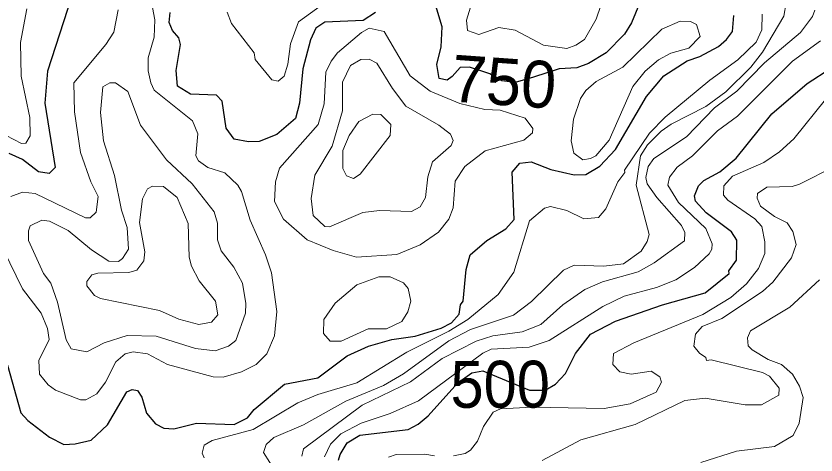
# Model space of a CAD drawing. Extents: x 763.2 to 816.8, y 7896.5 to 7952.7.
# Drawn here: x 788.764 to 791.494, y 7916.414 to 7917.911 of the extents above; entities that cross this region are included whole.
import ezdxf
from ezdxf.enums import TextEntityAlignment as Align

# ---------------------------------------------------------------- set-up
doc = ezdxf.new("R2010")
doc.units = 0
doc.header["$LTSCALE"] = 0.064
doc.layers.add('1', color=7, linetype='Continuous', lineweight=25)
doc.layers.add('2', color=7, linetype='Continuous', lineweight=13)
doc.layers.add('61', color=7, linetype='Continuous')

msp = doc.modelspace()

# ---------------------------------------------------------------- linework, layer by layer
at = {"layer": '1'}
for points in [[(788.9532, 7917.9764), (788.8718, 7917.7233), (788.862, 7917.6141), (788.8983, 7917.3951), (788.8775, 7917.3735), (788.8407, 7917.3792), (788.7863, 7917.4224), (788.7412, 7917.4422)], [(790.8995, 7917.9748), (790.8639, 7917.8884), (790.8401, 7917.8489), (790.7781, 7917.7858), (790.7169, 7917.7496), (790.6779, 7917.735), (790.6177, 7917.7315), (790.5297, 7917.7032), (790.4675, 7917.6845), (790.4219, 7917.6907), (790.3804, 7917.7136), (790.3119, 7917.7364), (790.2798, 7917.7354), (790.2521, 7917.7053), (790.2347, 7917.6927), (790.2079, 7917.6978), (790.1997, 7917.7465), (790.2143, 7917.8068), (790.2176, 7917.8744), (790.1967, 7917.9459)], [(788.7355, 7916.7201), (788.7801, 7916.558), (788.804, 7916.5314), (788.8784, 7916.4743), (788.9268, 7916.4498), (788.9662, 7916.4515), (789.0207, 7916.4639), (789.0758, 7916.5165), (789.1419, 7916.6289), (789.16, 7916.6367), (789.1789, 7916.6332), (789.194, 7916.6114), (789.2092, 7916.5563), (789.2405, 7916.5199), (789.2689, 7916.5047), (789.3025, 7916.5026), (789.3797, 7916.5217), (789.5084, 7916.5173), (789.5537, 7916.5401), (789.5769, 7916.5693), (789.6804, 7916.6548), (789.7937, 7916.6767), (789.894, 7916.7519), (789.9672, 7916.7846), (790.0468, 7916.8079), (790.1266, 7916.8196), (790.2143, 7916.8469), (790.2502, 7916.8647), (790.2761, 7916.8942), (790.2802, 7916.9254), (790.29, 7916.9386), (790.3001, 7917.047), (790.3132, 7917.0971), (790.3707, 7917.1453), (790.4355, 7917.1855), (790.464, 7917.2174), (790.4566, 7917.3787), (790.4832, 7917.4093), (790.5223, 7917.4142), (790.5884, 7917.3882), (790.6688, 7917.37), (790.7081, 7917.3705), (790.7563, 7917.3988), (790.809, 7917.4564), (790.9158, 7917.6372), (790.9741, 7917.707), (791.0544, 7917.7586), (791.0969, 7917.7733), (791.1615, 7917.8075), (791.1885, 7917.8313), (791.2082, 7917.8591), (791.2135, 7917.9131)], [(789.9909, 7917.9238), (789.9486, 7917.8963), (789.8175, 7917.8909), (789.7875, 7917.8696), (789.7687, 7917.8304), (789.7428, 7917.7311), (789.7311, 7917.6141), (789.7183, 7917.5613), (789.6535, 7917.507), (789.5939, 7917.4837), (789.5579, 7917.4818), (789.5085, 7917.4915), (789.4813, 7917.5291), (789.468, 7917.6209), (789.4481, 7917.6416), (789.3599, 7917.6446), (789.3154, 7917.6724), (789.3106, 7917.7251), (789.3251, 7917.8146), (789.3193, 7917.8372), (789.2977, 7917.8624), (789.2864, 7917.8893), (789.2905, 7917.9236)], [(789.8647, 7916.396), (789.8698, 7916.4158), (789.8937, 7916.4547), (789.9369, 7916.4811), (790.1027, 7916.5007), (790.1365, 7916.5183), (790.1704, 7916.5471), (790.2719, 7916.6599), (790.3198, 7916.6936), (790.3574, 7916.7011), (790.516, 7916.6347), (790.5699, 7916.6346), (790.6044, 7916.6555), (790.6387, 7916.6916), (790.6728, 7916.76), (790.7247, 7916.8262), (790.8101, 7916.8705), (790.9704, 7916.9262), (791.1155, 7916.9673), (791.1978, 7917.0325), (791.1962, 7917.0418), (791.2219, 7917.078), (791.2233, 7917.1461), (791.2048, 7917.1748), (791.1189, 7917.2394), (791.0827, 7917.2792), (791.0792, 7917.2974), (791.0922, 7917.3321), (791.1113, 7917.3498), (791.1655, 7917.3794), (791.2207, 7917.4263), (791.3431, 7917.5781), (791.464, 7917.6809), (791.5445, 7917.7334)]]:
    msp.add_lwpolyline(points, dxfattribs=at)
at = {"layer": '2'}
for points in [[(789.2187, 7918.0024), (789.2382, 7917.8982), (789.2352, 7917.8397), (789.2153, 7917.7686), (789.2153, 7917.7241), (789.2237, 7917.6832), (789.236, 7917.6583), (789.3661, 7917.5538), (789.3844, 7917.5096), (789.3782, 7917.4348), (789.3871, 7917.4168), (789.4183, 7917.3947), (789.4771, 7917.3765), (789.5207, 7917.3341), (789.5339, 7917.3124), (789.5635, 7917.2145), (789.6157, 7917.0969), (789.636, 7917.0357), (789.6539, 7916.903), (789.646, 7916.8201), (789.6204, 7916.759), (789.5839, 7916.7229), (789.5331, 7916.697), (789.4709, 7916.6797), (789.4373, 7916.6799), (789.2805, 7916.7228), (789.2129, 7916.7586), (789.1637, 7916.7652), (789.1364, 7916.7584), (789.1051, 7916.732), (789.0689, 7916.6617), (789.0399, 7916.6227), (789.0029, 7916.6015), (788.9843, 7916.6022), (788.8986, 7916.6348), (788.874, 7916.6531), (788.844, 7916.6897), (788.8423, 7916.7355), (788.8767, 7916.8078), (788.8719, 7916.8451), (788.8501, 7916.8977), (788.7864, 7916.9805), (788.7211, 7917.1138)], [(789.4848, 7917.9246), (789.4989, 7917.8864), (789.5766, 7917.7854), (789.5801, 7917.7634), (789.6368, 7917.6937), (789.6584, 7917.689), (789.6795, 7917.7058), (789.6919, 7917.747), (789.7003, 7917.816), (789.7283, 7917.8918), (789.8589, 7917.9875)], [(788.8108, 7917.5648), (788.7816, 7917.7062), (788.7797, 7917.8212), (788.8011, 7917.9362)], [(790.3195, 7917.956), (790.3017, 7917.8975), (790.3051, 7917.8621), (790.3437, 7917.8482)], [(790.6745, 7917.8123), (790.7033, 7917.8315), (790.7432, 7917.9001), (790.7598, 7917.9469)], [(791.3924, 7917.9568), (791.3844, 7917.9108), (791.3111, 7917.7877), (791.2712, 7917.7365), (791.186, 7917.6528), (791.1177, 7917.6029), (790.9994, 7917.542), (790.9652, 7917.5181), (790.9182, 7917.4716), (790.8948, 7917.4349), (790.88, 7917.3337), (790.9242, 7917.166)], [(788.7462, 7917.2953), (788.7867, 7917.3105), (788.8297, 7917.306), (789.001, 7917.2223), (789.0166, 7917.2225), (789.0378, 7917.2426), (789.0442, 7917.2952), (789.0198, 7917.3454), (788.9847, 7917.4462), (788.9636, 7917.5843), (788.961, 7917.6832), (789.0711, 7917.8145), (789.0974, 7917.8561), (789.1132, 7917.9322)], [(791.3105, 7917.9172), (791.3088, 7917.8647), (791.2891, 7917.8218), (791.2272, 7917.7618), (791.1315, 7917.692), (790.9792, 7917.5661), (790.925, 7917.5117), (790.8402, 7917.3859), (790.8417, 7917.3776), (790.818, 7917.3459), (790.7767, 7917.2539), (790.7517, 7917.224), (790.7012, 7917.219), (790.6433, 7917.2482), (790.5873, 7917.2611), (790.5671, 7917.2553), (790.5166, 7917.2126), (790.4628, 7917.037), (790.4097, 7916.9607), (790.3059, 7916.8762), (790.2406, 7916.8358), (790.0973, 7916.7649), (789.9273, 7916.6593), (789.7938, 7916.6205), (789.726, 7916.5914), (789.5729, 7916.5003), (789.433, 7916.4635), (789.406, 7916.4476), (789.3995, 7916.4198), (789.4063, 7916.4042)], [(789.7397, 7916.4092), (789.7447, 7916.4347), (789.9455, 7916.5831), (790.1099, 7916.6637), (790.2181, 7916.7434), (790.3342, 7916.8018), (790.3906, 7916.8206), (790.4912, 7916.8343), (790.5552, 7916.8586), (790.6303, 7916.9261), (790.7046, 7916.9779), (790.7647, 7917.0039), (790.8872, 7917.039), (790.9414, 7917.0695), (791.0455, 7917.1447), (791.046, 7917.1733), (791.0348, 7917.1968), (790.9503, 7917.2917), (790.918, 7917.3388), (790.9131, 7917.3608), (790.9214, 7917.3981), (790.94, 7917.4255), (791.0521, 7917.4992), (791.1475, 7917.5978), (791.223, 7917.6554), (791.3178, 7917.7516), (791.4404, 7917.8548), (791.4822, 7917.9094), (791.4897, 7917.9311)], [(790.3437, 7917.8482), (790.411, 7917.8725), (790.4668, 7917.8629), (790.5635, 7917.8119), (790.6431, 7917.8009), (790.6745, 7917.8123)], [(791.0199, 7917.3961), (791.0728, 7917.4345), (791.1577, 7917.5192), (791.226, 7917.57), (791.413, 7917.7577), (791.5089, 7917.8264)], [(791.5266, 7917.6268), (791.4184, 7917.4927), (791.3686, 7917.4476), (791.3155, 7917.4111), (791.2091, 7917.3644), (791.1793, 7917.3324), (791.1777, 7917.3), (791.1929, 7917.2826), (791.2854, 7917.2191), (791.309, 7917.1928), (791.3188, 7917.1408), (791.3186, 7917.1015), (791.2973, 7917.0495), (791.2569, 7916.9975), (791.203, 7916.9512), (791.1073, 7916.8927), (790.8725, 7916.7966), (790.803, 7916.7601), (790.8002, 7916.7228), (790.8243, 7916.6976), (790.8627, 7916.6897), (790.9314, 7916.6994), (790.9611, 7916.6804), (790.9666, 7916.6626), (790.9488, 7916.6275), (790.8594, 7916.5879), (790.7704, 7916.5717), (790.5257, 7916.5768), (790.4173, 7916.5707), (790.3923, 7916.5594), (790.3592, 7916.5104), (790.3389, 7916.4606), (790.3147, 7916.43), (790.2971, 7916.4187), (790.2566, 7916.4102)], [(788.6513, 7917.5098), (788.7031, 7917.5176), (788.7828, 7917.4768), (788.798, 7917.4773), (788.8124, 7917.5027), (788.8108, 7917.5648)], [(790.5593, 7916.3946), (790.6908, 7916.465), (790.8771, 7916.5182), (791.0461, 7916.5991), (791.115, 7916.6073), (791.2517, 7916.5845), (791.3078, 7916.5844), (791.3667, 7916.6183), (791.3676, 7916.6422), (791.3351, 7916.683), (791.3109, 7916.6948), (791.1356, 7916.7384), (791.1206, 7916.7358), (791.1179, 7916.7468), (791.0956, 7916.7607), (791.0764, 7916.7847), (791.0827, 7916.8264), (791.1054, 7916.852), (791.1722, 7916.8794), (791.3111, 7916.971), (791.3468, 7917.0037), (791.4095, 7917.0863), (791.4256, 7917.1321), (791.4143, 7917.1767), (791.3951, 7917.2063), (791.3525, 7917.2269), (791.3038, 7917.2621), (791.2928, 7917.2895), (791.2937, 7917.3053), (791.3258, 7917.3271), (791.4118, 7917.3302), (791.4372, 7917.3372), (791.5589, 7917.3994)], [(791.1391, 7917.1338), (791.1174, 7917.1866), (791.024, 7917.2752), (790.9886, 7917.3337), (790.9935, 7917.3617), (791.0199, 7917.3961)], [(790.9242, 7917.166), (790.9177, 7917.1416), (790.8972, 7917.1095), (790.8365, 7917.066), (790.7699, 7917.0577), (790.6681, 7917.0608)], [(789.8168, 7916.4071), (789.8374, 7916.4507), (789.8724, 7916.4854), (789.9416, 7916.5219), (790.0409, 7916.555), (790.1378, 7916.5979), (790.3569, 7916.7608), (790.3848, 7916.775), (790.5149, 7916.7818), (790.5836, 7916.8046), (790.7661, 7916.9208), (790.8393, 7916.9552), (790.95, 7916.9853), (791.0158, 7917.0115), (791.0789, 7917.0528), (791.1288, 7917.0996), (791.138, 7917.1159), (791.1391, 7917.1338)], [(790.6681, 7917.0608), (790.6327, 7917.0448), (790.5234, 7916.9377), (790.461, 7916.8902), (790.3152, 7916.8417), (790.2408, 7916.8029), (790.0863, 7916.6908), (790.0178, 7916.6505), (789.889, 7916.5975), (789.7447, 7916.5164), (789.6437, 7916.4738), (789.6179, 7916.4495), (789.6083, 7916.4221), (789.6737, 7916.3198)], [(791.5056, 7917.0113), (791.4043, 7916.9179), (791.2701, 7916.8374), (791.2598, 7916.8128), (791.2626, 7916.7864), (791.2753, 7916.7727), (791.3307, 7916.7396), (791.376, 7916.7222), (791.4133, 7916.6889), (791.4371, 7916.6484), (791.4501, 7916.6097), (791.4362, 7916.5225), (791.4163, 7916.4802), (791.3517, 7916.4431), (791.2224, 7916.427), (791.1009, 7916.3879)], [(790.192, 7916.4102), (790.1586, 7916.4167), (790.0607, 7916.415), (790.0349, 7916.4065)]]:
    msp.add_lwpolyline(points, dxfattribs=at)
for points in [[(790.6665, 7917.5594), (790.6904, 7917.63), (790.7089, 7917.6573), (790.7431, 7917.6883), (790.835, 7917.7373), (790.9677, 7917.8665), (791.0303, 7917.8941), (791.065, 7917.8925), (791.086, 7917.8829), (791.0986, 7917.8411), (791.0601, 7917.8022), (790.9981, 7917.7845), (790.9568, 7917.7623), (790.9108, 7917.7227), (790.8685, 7917.671), (790.7883, 7917.4873), (790.7425, 7917.4346), (790.7244, 7917.4248), (790.6982, 7917.4209), (790.6679, 7917.4431), (790.6582, 7917.485)], [(789.8465, 7917.1115), (789.9259, 7917.0889), (790.0632, 7917.0972), (790.1434, 7917.1307), (790.2056, 7917.1742), (790.2409, 7917.2178), (790.2555, 7917.2572), (790.2621, 7917.3479), (790.2955, 7917.3983), (790.3651, 7917.4516), (790.4971, 7917.4883), (790.5261, 7917.5125), (790.5274, 7917.5279), (790.5009, 7917.5626), (790.4156, 7917.5899), (790.3641, 7917.5923), (790.2781, 7917.6128), (790.1772, 7917.6555), (790.1095, 7917.7071), (790.0207, 7917.8591), (789.9692, 7917.8695), (789.9433, 7917.8547), (789.8612, 7917.7857), (789.8394, 7917.7571), (789.8215, 7917.7193), (789.8152, 7917.6122), (789.7946, 7917.5413), (789.6626, 7917.3926), (789.6493, 7917.346), (789.6462, 7917.2784), (789.6769, 7917.2187), (789.7571, 7917.1478)], [(790.2491, 7917.4691), (790.2554, 7917.4866), (790.2468, 7917.5083), (790.2067, 7917.5389), (790.0939, 7917.604), (790.0489, 7917.6637), (789.9958, 7917.7508), (789.9686, 7917.7641), (789.9402, 7917.7626), (789.9055, 7917.7423), (789.878, 7917.6852), (789.8777, 7917.5876), (789.8432, 7917.4676), (789.784, 7917.3683), (789.7708, 7917.2887), (789.7775, 7917.2304), (789.8175, 7917.1927), (789.8341, 7917.1925), (789.9472, 7917.2405), (790.0041, 7917.2483), (790.1134, 7917.2441), (790.1428, 7917.2609), (790.1616, 7917.2927), (790.1687, 7917.3624), (790.185, 7917.4143)], [(788.9357, 7916.8068), (788.906, 7916.935), (788.8832, 7917), (788.8574, 7917.0325), (788.8067, 7917.1458), (788.8063, 7917.1783), (788.813, 7917.1955), (788.8518, 7917.2154), (788.8787, 7917.2118), (788.9424, 7917.1792), (789.0219, 7917.1132), (789.0804, 7917.0744), (789.114, 7917.0737), (789.1272, 7917.0836), (789.1476, 7917.1158), (789.143, 7917.1902), (789.1235, 7917.2493), (789.1004, 7917.3677), (789.0626, 7917.486), (789.0526, 7917.582), (789.0608, 7917.67), (789.0843, 7917.6836), (789.1034, 7917.6836), (789.1461, 7917.654), (789.1891, 7917.5393), (789.2778, 7917.421), (789.3647, 7917.3387), (789.4403, 7917.2434), (789.4518, 7917.2046), (789.452, 7917.1481), (789.4646, 7917.11), (789.507, 7917.0547), (789.5374, 7916.9995), (789.5488, 7916.9305), (789.547, 7916.8976), (789.5142, 7916.8047), (789.489, 7916.7846), (789.4434, 7916.7687), (789.3763, 7916.7767), (789.2422, 7916.8191), (789.1436, 7916.8209), (789.0654, 7916.7968), (789.0055, 7916.7656), (788.9525, 7916.7754)], [(790.0402, 7917.5038), (790.0435, 7917.5413), (790.0094, 7917.5754), (789.9819, 7917.5769), (789.9342, 7917.5512), (789.9009, 7917.5036), (789.8792, 7917.4531), (789.8793, 7917.391), (789.8918, 7917.3662), (789.9157, 7917.3568), (789.9384, 7917.3717)], [(789.2541, 7916.9065), (789.3198, 7916.8771), (789.3875, 7916.8587), (789.4315, 7916.8672), (789.4532, 7916.8914), (789.4453, 7916.9387), (789.3891, 7917.0073), (789.3627, 7917.0574), (789.355, 7917.0889), (789.3516, 7917.2033), (789.3137, 7917.2926), (789.2672, 7917.3302), (789.2296, 7917.3304), (789.2126, 7917.3222), (789.1957, 7917.2875), (789.1857, 7917.2066), (789.2036, 7917.1072), (789.2003, 7917.0758), (789.1763, 7917.0441), (789.1489, 7917.0363), (789.043, 7917.0341), (789.0232, 7917.0278), (789.0063, 7917.0056), (789.0058, 7916.9904), (789.0325, 7916.9583), (789.0525, 7916.9472)], [(789.8531, 7916.9314), (789.9273, 7916.9944), (790.0015, 7917.0215), (790.0409, 7917.0213), (790.086, 7917.0015), (790.1017, 7916.9818), (790.1108, 7916.9384), (790.101, 7916.9016), (790.081, 7916.8692), (790.0281, 7916.8436), (789.9652, 7916.8439), (789.8733, 7916.8018), (789.8357, 7916.8025), (789.8137, 7916.828), (789.814, 7916.8762)]]:
    msp.add_lwpolyline(points, close=True, dxfattribs=at)

# ---------------------------------------------------------------- texts
at = {"layer": '61'}
msp.add_text('750', height=0.16, rotation=355.92, dxfattribs=at).set_placement((790.4232, 7917.6075), align=Align.CENTER)
at = {"layer": '61', "width": 0.95}
msp.add_text('500', height=0.16, rotation=0.132, dxfattribs=at).set_placement((790.4163, 7916.575), align=Align.CENTER)

doc.saveas('drawing.dxf')
